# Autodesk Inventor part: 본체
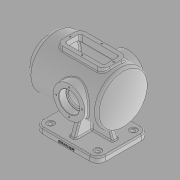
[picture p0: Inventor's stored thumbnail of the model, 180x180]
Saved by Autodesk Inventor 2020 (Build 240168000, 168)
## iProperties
Created: 2021-11
Part Number: 본체
Material: 일반
Document SubType Name: Modeling
Designer: Administrator
Density: 1 g/cm^3
Appearance: 기본값
Author: Administrator
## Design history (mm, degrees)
sketch "스케치1"
  geometry: L1 (-80, 65)-(80, 65); L2 (80, 65)-(80, -65); L3 (80, -65)-(-80, -65); L4 (-80, -65)-(-80, 65); L5 (-80, 65)-(80, -65); L6 (80, 65)-(-80, -65); 1 further point
  constraints: 12 end point, 2 midpoint, 2 parallel, 1 horizontal, 1 perpendicular
  dimensions: "d0" = 160 distance of L2.end L3.end; "d1" = 130 distance of L1.end L2.end
extrude "돌출1" new body sketch "스케치1" distance "d2" = 14; taper "d3" = 0 deg
sketch "스케치2"
  geometry: L1 (110, 114)-(110, 161.5); L2 (110, 161.5)-(100, 161.5); L3 (100, 161.5)-(100, 179); L4 (100, 179)-(-75.993, 179); L5 (110, 114)-(-100, 114); L6 (80, 0)-(80, 14) reference; L7 (85, 169)-(-71.239, 169); L8 (110, 146.5)-(85, 146.5); L9 (85, 146.5)-(85, 169); A1 r 100 centre (0, 114) between (-75.993, 179) and (-100, 114); A2 r 90 centre (0, 114) between (-71.239, 169) and (-90, 114); 2 further points
  constraints: 16 end point, 4 perpendicular, 4 point on circle, 2 centre point, 2 horizontal, 2 point on line, 1 horizontal alignment, 1 midpoint, 1 vertical
  dimensions: "d4" = 210 distance of L1.start L5.end; "d5" = 95 diameter of L2 L5; "d6" = 130 diameter of L4 L5; "d7" = 100 radius of A1; "d8" = 10 distance between parallel lines of L1 L3; "d9" = 114 vertical distance of L1.start point (0, 0); "d10" = 30 distance between parallel lines of L1 L6; "d11" = 10 radial gap between concentric circles of A1 A2; "d12" = 65 diameter of L8 L5; "d13" = 25 distance between parallel lines of L9 L1; "d14" = 110 diameter of L7 L5
revolve "회전1" sketch "스케치2" stored, may be unused: angle "d15" = 90 deg
sketch "스케치3"
  geometry: L1 (-7, 7)-(7, 7); L2 (7, 7)-(7, -7); L3 (7, -7)-(-7, -7); L4 (-7, -7)-(-7, 7); L5 (-7, 7)-(7, -7); L6 (7, 7)-(-7, -7); 1 further point
  constraints: 12 end point, 2 midpoint, 2 parallel, 1 horizontal, 1 perpendicular
  dimensions: "d16" = 14 distance of L2.end L3.end; "d17" = 14 distance of L1.end L2.end
extrude "돌출2" join sketch "스케치3" stored distance "d18" = 14; taper "d19" = 0 deg
sketch "스케치4"
  geometry: L1 (-80, 14)-(80, 14) reference; L2 (-60, 14)-(-51.998, 35.984); 1 further point
  constraints: 2 end point, 1 point on line
  dimensions: "d20" = 60 horizontal distance of L2.start point (0, 0); "d21" = 110 deg angle of L2 L1
feature "리브1" sketch "스케치4" dims "d22" = 1, "d23" = 14, "d24" = 0, "d25" = 0, "d26" = 1, "d27" = 1
sketch "스케치5"
  geometry: L1 (65, 14)-(-65, 14) reference; L2 (50, 14)-(39.5, 42.849); 1 further point
  constraints: 2 end point, 1 point on line
  dimensions: "d28" = 50 horizontal distance of L2.start point (0, 0); "d29" = 110 deg angle of L1 L2
feature "리브2" sketch "스케치5" dims "d30" = 1, "d31" = 14, "d32" = 0, "d33" = 0, "d34" = 1, "d35" = 1
node "작업 평면1"
sketch "스케치6"
  geometry: L1 (-60, 30)-(60, 30); L2 (60, 30)-(60, -30); L3 (60, -30)-(-60, -30); L4 (-60, -30)-(-60, 30); L5 (-110, 47.5)-(-110, -47.5) reference; 3 further points
  constraints: 8 end point, 2 horizontal alignment, 2 midpoint, 2 parallel, 1 horizontal, 1 perpendicular
  dimensions: "d37" = 60 distance between parallel lines of L3 L1; "d38" = 120 distance between parallel lines of L2 L4; "d39" = 50 distance between parallel lines of L4 L5
extrude "돌출3" join sketch "스케치6" stored distance "d40" = 14; taper "d41" = 0 deg
sketch "스케치7"
  geometry: L1 (60, 30)-(-60, 30) reference; L2 (-60, 30)-(-60, -30) reference; L3 (-60, -30)-(60, -30) reference; L4 (60, -30)-(60, 30) reference; L5 (-50, 20)-(50, 20); L6 (50, 20)-(50, -20); L7 (50, -20)-(-50, -20); L8 (-50, -20)-(-50, 20); 1 further point
  constraints: 8 end point, 3 other
  dimensions: "d42" = 10 distance between parallel lines of L1 L5
extrude "돌출4" cut sketch "스케치7" stored distance "d43" = 14; taper "d44" = 0 deg
node "작업 평면2"
sketch "스케치8"
  geometry: L1 (-110, 161.5)-(-110, 66.5) reference; C1 r 40 at (17, 114); 2 further points
  constraints: 1 centre point, 1 horizontal alignment, 1 midpoint
  dimensions: "d46" = 80 diameter of C1; "d47" = 127 distance from line of L1 C1.centre
extrude "돌출5" join sketch "스케치8" stored distance "d48" = 14; taper "d49" = 0 deg
sketch "스케치9"
  geometry: C1 r 40 at (0, 0) reference; C2 r 26 at (0, 0); 1 further point
  constraints: 1 centre point, 1 coincident
  dimensions: "d50" = 52 diameter of C2
extrude "돌출6" cut sketch "스케치9" distance "d51" = 18; taper "d52" = 0 deg
sketch "스케치10"
  geometry: C1 r 26 at (0, 0) reference; C2 r 21 at (0, 0); 1 further point
  constraints: 1 centre point, 1 coincident
  dimensions: "d53" = 42 diameter of C2
extrude "돌출7" cut sketch "스케치10" extent not by distance; stored distance "d54" = 18; taper "d55" = 0 deg
sketch "스케치11" dims "d56" = 65
  geometry: L1 (0, 0)-(0, 32.5); C1 r 26 at (0, 0) reference; 2 further points
  constraints: 2 coincident, 2 end point, 1 vertical, 1 vertical alignment, 2 other
hole "구멍1" sketch "스케치11" at (0, 32.5) diameter "d57" = 3.45873; stored, may be unused: countersink angle "d61" = 90 deg, drill point angle "d63" = 118 deg; dims "d58" = 11, "d59" = 4, "d60" = 2, "d62" = 13
fillet "모깎기1" dims "d67" = 20
sketch "스케치12"
  geometry: A1 r 20 centre (60, 45) between (80, 45) and (60, 65) reference; A2 r 20 centre (-60, 45) between (-60, 65) and (-80, 45) reference; A3 r 20 centre (-60, -45) between (-80, -45) and (-60, -65) reference; A4 r 20 centre (60, -45) between (60, -65) and (80, -45) reference; 5 further points
  constraints: 4 coincident
hole "구멍2" sketch "스케치12" at (60, 45), (-60, 45), (-60, -45), (60, -45) diameter "d68" = 9; stored, may be unused: countersink angle "d72" = 90 deg, drill point angle "d74" = 118 deg; dims "d69" = 11, "d70" = 18, "d71" = 2, "d73" = 13
fillet "모깎기2" dims "d75" = 3
fillet "모깎기3" dims "d76" = 3
fillet "모깎기4" dims "d77" = 10
fillet "모깎기5" dims "d78" = 3
fillet "모깎기6" dims "d79" = 3
fillet "모깎기7" dims "d80" = 15
fillet "모깎기8" dims "d81" = 5
fillet "모깎기9" dims "d82" = 3
sketch "스케치13"
  geometry: L1 (-23, 75)-(57, 75) reference; L2 (17, 75)-(17, 84.959); L3 (-45, 20)-(45, 20) reference; L4 (45, -20)-(-45, -20) reference; 5 further points
  constraints: 2 end point, 2 horizontal alignment, 1 midpoint, 1 vertical
  dimensions: "d83" = 50 distance of point (0, -25) point (0, 25); "d84" = 17 distance from line of point (0, 25) L2; "d85" = 5 distance from line of point (0, 25) L3; "d86" = 5 distance from line of L4 point (0, -25); "d87" = 55 horizontal distance of point (-55, 0) point (0, 25); "d88" = 55 horizontal distance of point (0, 25) point (55, 0)
hole "구멍3" sketch "스케치13" at (0, 25), (0, -25), (55, 0), (-55, 0) diameter "d89" = 3.45873; stored, may be unused: countersink angle "d93" = 90 deg, drill point angle "d95" = 118 deg; dims "d90" = 9, "d91" = 18, "d92" = 2, "d94" = 11
fillet "모깎기10" dims "d96" = 3
chamfer "모따기1" distance "d97" = 1; stored, may be unused: second distance "d98" = 2, angle "d99" = 45 deg
chamfer "모따기2" distance "d100" = 1; stored, may be unused: second distance "d101" = 2, angle "d102" = 45 deg
fillet "모깎기11" dims "d103" = 0.3
sketch "스케치14"
  geometry: L1 (39.261, 8.002)-(80.739, 8.002); L2 (80.739, 8.002)-(80.739, 1.998); L3 (80.739, 1.998)-(39.261, 1.998); L4 (39.261, 1.998)-(39.261, 8.002); L5 (39.261, 8.002)-(80.739, 1.998); L6 (0, 0)-(120, 0) reference; 3 further points
  constraints: 2 end point, 2 midpoint, 1 vertical alignment, 2 other
  dimensions: "d104" = 5 distance from line of point (60, 5) L6
feature "엠보싱1" sketch "스케치14" dims "d11" = 10, "d105" = 0.5, "d106" = 0
sketch "스케치15" dims "d107" = 80
  geometry: L1 (0, 0)-(40, 0); C1 r 47.5 at (0, 0) reference; 2 further points
  constraints: 2 coincident, 2 end point, 1 horizontal, 1 horizontal alignment, 2 other
hole "구멍4" sketch "스케치15" at (40, 0) diameter "d108" = 3.45873; stored, may be unused: countersink angle "d112" = 90 deg, drill point angle "d114" = 118 deg; dims "d109" = 11, "d110" = 18, "d111" = 2, "d113" = 13
fillet "모깎기12" dims "d118" = 3
node "솔리드1"
mirror "미러1"
mirror "미러2"
mirror "미러3"
mirror "미러4"
pattern_circular "원형 패턴1" dims angle "d65" = 360 deg
mirror "미러5"
pattern_circular "원형 패턴2" dims angle "d116" = 360 deg
node "투영된 루프1"
node "투영된 루프2"
feature "A9D066F2-1C7D-4E18-AEED-F7BC21143FA4" dims "d68" = 9, "d69" = 11, "d70" = 18, "d71" = 2, "d72" = 90 deg, "d73" = 13, "d74" = 118 deg
other parameters: "d36" = 184, "d45" = -75
